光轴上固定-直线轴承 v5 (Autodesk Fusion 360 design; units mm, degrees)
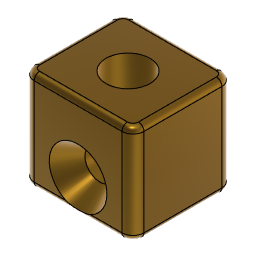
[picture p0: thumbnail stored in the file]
sketch "草图1" plane through (0, 0, 0) normal (0, 1, 0) x axis (1, 0, 0)
  line L1 (20, 0) -> (0, 0)
  line L2 (20, -18) -> (20, 0)
  line L3 (0, -18) -> (20, -18)
  line L4 (0, 0) -> (0, -18)
  circle C1 centre (10, -5.75) radius 2.75
  circle C2 centre (10, -5.75) radius 5.25
  point P1 (0, 0)
  point P2 (0, 0)
  point P3 (20, 0)
  point P5 (0, -18)
  horizontal L1
  vertical L2
  horizontal L3
  vertical L4
  coincident P1 P2
  concentric C1 C2
  dimension "d1" distance P2 P3 = 20
  dimension "d2" distance P2 P5 = 18
  dimension "d5" diameter C1 = 5.5
  dimension "d6" diameter C2 = 10.5
extrude "拉伸1" new body sketch "草图1" along normal blind 20
work_plane "工作平面" sketch "草图1" AlongDistance 4
sketch "草图2" plane through (0, 4, 0) normal (0, 1, 0) x axis (1, 0, 0)
  circle C1 centre (10, -5.75) radius 2.75
  point P2 (10, -5.75)
  point P3 (10, -5.75)
  coincident P2 P3
  dimension "d13" diameter C1 = 5.5
loft "放样" sketch "草图2" + "草图1"
extrude "拉伸3" cut of existing geometry blind -16
sketch "草图3" plane through (0, 0, 18) normal (0, 0, 1) x axis (-1, 0, 0)
  line L1 (-20, 0) -> (0, 0)
  line L2 (-20, -20) -> (-20, 0)
  line L3 (0, -20) -> (-20, -20)
  line L4 (0, 0) -> (0, -20)
  line L5 (-20, 0) -> (0, 0)
  line L6 (-20, -18.2) -> (-20, 0)
  line L7 (0, -18.2) -> (-20, -18.2)
  line L8 (0, 0) -> (0, -18.2)
  line L9 (-20, -18.2) -> (0, 0)
  line L10 (-20, 0) -> (0, -18.2)
  circle C1 centre (-10, -9.1) radius 4
  point P9 (-20, -18.2)
  point P2 (0, 0)
  point P7 (0, 0)
  point P11 (0, 0)
  point P3 (-20, 0)
  point P12 (-20, 0)
  point P6 (-10, -9.1)
  point P10 (0, -18.2)
  horizontal L5
  vertical L6
  horizontal L7
  vertical L8
  coincident L2 P9
  coincident P2 P7
  coincident P2 P11
  coincident P3 P12
  coincident P6 L9
  coincident P6 L10
  dimension "d16" diameter C1 = 8
  dimension "d23" distance P7 P10 = 18.2
extrude "拉伸4" cut sketch "草图3" profile of C1 against normal blind 9
extrude "拉伸5" cut of existing geometry blind -1.8
fillet "圆角1" radius 2
fillet "圆角2" radius 2
fillet "圆角3" radius 1
fillet "圆角4" radius 1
